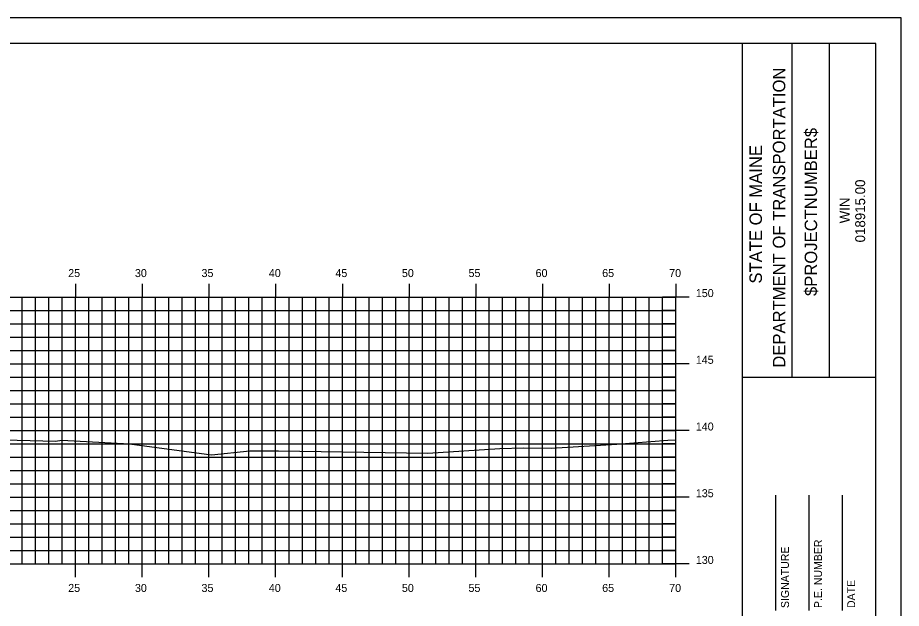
# Model space of a CAD drawing. Extents: x 851417 to 851588, y 365876 to 365986.
# Drawn here: x 851520.6 to 851586.8, y 365941.5 to 365985.8 of the extents above; entities that cross this region are included whole.
import ezdxf

# ---------------------------------------------------------------- set-up
doc = ezdxf.new("R2010")
doc.units = 0
for name, color, linetype in [('BORDER', 7, 'Continuous'), ('H_V ANNOTATION', 7, 'Continuous'), ('MAJOR', 7, 'Continuous'), ('MINOR', 7, 'Continuous'), ('PLOT BOUNDARY', 7, 'Continuous'), ('S_Roadway_Centerline', 7, 'Continuous')]:
    doc.layers.add(name, color=color, linetype=linetype)

msp = doc.modelspace()

# ---------------------------------------------------------------- linework, layer by layer
at = {"layer": 'BORDER'}
for p, q in [((851574.899, 365878.833), (851574.899, 365983.833)), ((851578.627, 365958.83), (851578.627, 365983.83)), ((851581.422, 365958.83), (851581.422, 365983.83)), ((851574.9, 365958.827), (851584.899, 365958.827)), ((851577.399, 365941.336), (851577.399, 365949.984)), ((851579.899, 365941.336), (851579.899, 365949.984)), ((851582.399, 365941.336), (851582.399, 365949.984))]:
    msp.add_line(p, q, dxfattribs=at)
msp.add_lwpolyline([(851424.899, 365878.833), (851584.899, 365878.833), (851584.899, 365983.833), (851424.899, 365983.833)], close=True, dxfattribs=at)
at = {"layer": 'MAJOR'}
for p, q in [((851524.898, 365965.835), (851524.898, 365964.833)), ((851529.898, 365965.835), (851529.898, 365964.833)), ((851534.898, 365965.835), (851534.898, 365964.833)), ((851539.898, 365965.835), (851539.898, 365964.833)), ((851544.898, 365965.835), (851544.898, 365964.833)), ((851549.898, 365965.835), (851549.898, 365964.833)), ((851554.898, 365965.835), (851554.898, 365964.833)), ((851559.898, 365965.835), (851559.898, 365964.833)), ((851564.898, 365965.835), (851564.898, 365964.833)), ((851569.898, 365965.835), (851569.898, 365964.833)), ((851429.898, 365964.833), (851569.898, 365964.833)), ((851429.898, 365964.833), (851569.898, 365964.833)), ((851524.898, 365944.833), (851524.898, 365964.833)), ((851529.898, 365944.833), (851529.898, 365964.833)), ((851534.898, 365944.833), (851534.898, 365964.833)), ((851539.898, 365944.833), (851539.898, 365964.833)), ((851544.898, 365944.833), (851544.898, 365964.833)), ((851549.898, 365944.833), (851549.898, 365964.833)), ((851554.898, 365944.833), (851554.898, 365964.833)), ((851559.898, 365944.833), (851559.898, 365964.833)), ((851564.898, 365944.833), (851564.898, 365964.833)), ((851570.9, 365964.833), (851568.896, 365964.833)), ((851569.898, 365944.833), (851569.898, 365964.833)), ((851569.898, 365944.833), (851569.898, 365964.833)), ((851429.898, 365959.833), (851569.898, 365959.833)), ((851570.9, 365959.833), (851568.896, 365959.833)), ((851429.898, 365954.833), (851569.898, 365954.833)), ((851570.9, 365954.833), (851568.896, 365954.833)), ((851429.898, 365949.833), (851569.898, 365949.833)), ((851570.9, 365949.833), (851568.896, 365949.833)), ((851429.898, 365944.833), (851569.898, 365944.833)), ((851429.898, 365944.833), (851569.898, 365944.833)), ((851524.898, 365943.831), (851524.898, 365944.833)), ((851529.898, 365943.831), (851529.898, 365944.833)), ((851534.898, 365943.831), (851534.898, 365944.833)), ((851539.898, 365943.831), (851539.898, 365944.833)), ((851544.898, 365943.831), (851544.898, 365944.833)), ((851549.898, 365943.831), (851549.898, 365944.833)), ((851554.898, 365943.831), (851554.898, 365944.833)), ((851559.898, 365943.831), (851559.898, 365944.833)), ((851564.898, 365943.831), (851564.898, 365944.833)), ((851570.9, 365944.833), (851568.896, 365944.833)), ((851569.898, 365943.831), (851569.898, 365944.833))]:
    msp.add_line(p, q, dxfattribs=at)
at = {"layer": 'MINOR'}
for p, q in [((851520.898, 365944.833), (851520.898, 365964.833)), ((851521.898, 365944.833), (851521.898, 365964.833)), ((851522.898, 365944.833), (851522.898, 365964.833)), ((851523.898, 365944.833), (851523.898, 365964.833)), ((851525.898, 365944.833), (851525.898, 365964.833)), ((851526.898, 365944.833), (851526.898, 365964.833)), ((851527.898, 365944.833), (851527.898, 365964.833)), ((851528.898, 365944.833), (851528.898, 365964.833)), ((851530.898, 365944.833), (851530.898, 365964.833)), ((851531.898, 365944.833), (851531.898, 365964.833)), ((851532.898, 365944.833), (851532.898, 365964.833)), ((851533.898, 365944.833), (851533.898, 365964.833)), ((851535.898, 365944.833), (851535.898, 365964.833)), ((851536.898, 365944.833), (851536.898, 365964.833)), ((851537.898, 365944.833), (851537.898, 365964.833)), ((851538.898, 365944.833), (851538.898, 365964.833)), ((851540.898, 365944.833), (851540.898, 365964.833)), ((851541.898, 365944.833), (851541.898, 365964.833)), ((851542.898, 365944.833), (851542.898, 365964.833)), ((851543.898, 365944.833), (851543.898, 365964.833)), ((851545.898, 365944.833), (851545.898, 365964.833)), ((851546.898, 365944.833), (851546.898, 365964.833)), ((851547.898, 365944.833), (851547.898, 365964.833)), ((851548.898, 365944.833), (851548.898, 365964.833)), ((851550.898, 365944.833), (851550.898, 365964.833)), ((851551.898, 365944.833), (851551.898, 365964.833)), ((851552.898, 365944.833), (851552.898, 365964.833)), ((851553.898, 365944.833), (851553.898, 365964.833)), ((851555.898, 365944.833), (851555.898, 365964.833)), ((851556.898, 365944.833), (851556.898, 365964.833)), ((851557.898, 365944.833), (851557.898, 365964.833)), ((851558.898, 365944.833), (851558.898, 365964.833)), ((851560.898, 365944.833), (851560.898, 365964.833)), ((851561.898, 365944.833), (851561.898, 365964.833)), ((851562.898, 365944.833), (851562.898, 365964.833)), ((851563.898, 365944.833), (851563.898, 365964.833)), ((851565.898, 365944.833), (851565.898, 365964.833)), ((851566.898, 365944.833), (851566.898, 365964.833)), ((851567.898, 365944.833), (851567.898, 365964.833)), ((851568.898, 365944.833), (851568.898, 365964.833)), ((851429.898, 365963.833), (851569.898, 365963.833)), ((851569.898, 365963.833), (851568.896, 365963.833)), ((851429.898, 365962.833), (851569.898, 365962.833)), ((851569.898, 365962.833), (851568.896, 365962.833)), ((851429.898, 365961.833), (851569.898, 365961.833)), ((851569.898, 365961.833), (851568.896, 365961.833)), ((851429.898, 365960.833), (851569.898, 365960.833)), ((851569.898, 365960.833), (851568.896, 365960.833)), ((851429.898, 365958.833), (851569.898, 365958.833)), ((851569.898, 365958.833), (851568.896, 365958.833)), ((851429.898, 365957.833), (851569.898, 365957.833)), ((851569.898, 365957.833), (851568.896, 365957.833)), ((851429.898, 365956.833), (851569.898, 365956.833)), ((851569.898, 365956.833), (851568.896, 365956.833)), ((851429.898, 365955.833), (851569.898, 365955.833)), ((851569.898, 365955.833), (851568.896, 365955.833)), ((851429.898, 365953.833), (851569.898, 365953.833)), ((851569.898, 365953.833), (851568.896, 365953.833)), ((851429.898, 365952.833), (851569.898, 365952.833)), ((851569.898, 365952.833), (851568.896, 365952.833)), ((851429.898, 365951.833), (851569.898, 365951.833)), ((851569.898, 365951.833), (851568.896, 365951.833)), ((851429.898, 365950.833), (851569.898, 365950.833)), ((851569.898, 365950.833), (851568.896, 365950.833)), ((851429.898, 365948.833), (851569.898, 365948.833)), ((851569.898, 365948.833), (851568.896, 365948.833)), ((851429.898, 365947.833), (851569.898, 365947.833)), ((851569.898, 365947.833), (851568.896, 365947.833)), ((851429.898, 365946.833), (851569.898, 365946.833)), ((851569.898, 365946.833), (851568.896, 365946.833)), ((851429.898, 365945.833), (851569.898, 365945.833)), ((851569.898, 365945.833), (851568.896, 365945.833))]:
    msp.add_line(p, q, dxfattribs=at)
at = {"layer": 'PLOT BOUNDARY'}
msp.add_lwpolyline([(851416.805, 365875.774), (851586.805, 365875.774), (851586.805, 365985.774), (851416.805, 365985.774)], close=True, dxfattribs=at)
at = {"layer": 'S_Roadway_Centerline'}
msp.add_lwpolyline([(851518.599, 365954.164), (851523.381, 365954.029), (851523.863, 365954.099), (851528.949, 365953.839), (851535.086, 365953.012), (851537.964, 365953.31), (851538.278, 365953.307), (851540.109, 365953.3), (851551.308, 365953.141), (851556.7, 365953.497), (851558.489, 365953.54), (851560.546, 365953.498), (851565.485, 365953.819), (851569.298, 365954.107), (851569.898, 365954.139)], dxfattribs=at)

# ---------------------------------------------------------------- texts
at = {"layer": 'BORDER'}
for s, height, p in [('DEPARTMENT OF TRANSPORTATION', 0.93176, (851578.105, 365959.539)), ('$PROJECTNUMBER$', 0.93176, (851580.491, 365964.912)), ('STATE OF MAINE', 0.93176, (851576.354, 365965.845)), ('018915.00', 0.7453, (851584.094, 365968.931)), ('WIN', 0.7453, (851582.935, 365970.363)), ('P.E. NUMBER', 0.59055, (851580.859, 365941.528)), ('SIGNATURE', 0.5906, (851578.379, 365941.528)), ('DATE', 0.5906, (851583.34, 365941.528))]:
    msp.add_text(s, height=height, rotation=90, dxfattribs=at).set_placement(p)
at = {"layer": 'H_V ANNOTATION'}
for s, p in [('25', (851524.344, 365966.333)), ('30', (851529.347, 365966.333)), ('35', (851534.339, 365966.333)), ('40', (851539.385, 365966.333)), ('45', (851544.377, 365966.333)), ('50', (851549.363, 365966.333)), ('55', (851554.355, 365966.333)), ('60', (851559.385, 365966.333)), ('65', (851564.377, 365966.333)), ('70', (851569.4, 365966.333)), ('150', (851571.398, 365964.833)), ('145', (851571.398, 365959.833)), ('140', (851571.398, 365954.833)), ('135', (851571.398, 365949.833)), ('130', (851571.398, 365944.833)), ('25', (851524.344, 365942.733)), ('30', (851529.347, 365942.733)), ('35', (851534.339, 365942.733)), ('40', (851539.385, 365942.733)), ('45', (851544.377, 365942.733)), ('50', (851549.363, 365942.733)), ('55', (851554.355, 365942.733)), ('60', (851559.385, 365942.733)), ('65', (851564.377, 365942.733)), ('70', (851569.4, 365942.733))]:
    msp.add_text(s, height=0.6, dxfattribs=at).set_placement(p)

doc.saveas('drawing.dxf')
